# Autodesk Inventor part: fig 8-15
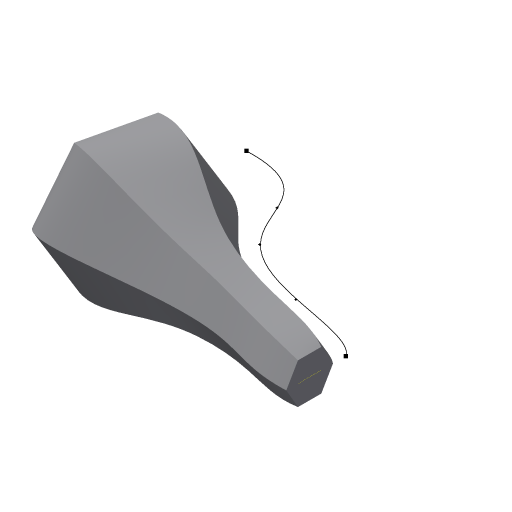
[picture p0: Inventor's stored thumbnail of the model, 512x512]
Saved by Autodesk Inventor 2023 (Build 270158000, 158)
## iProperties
Created: 2004-05
Part Number: fig 8-15
Document SubType Name: Modeling
Designer: CADCIM Technologies
Manufacturer: Standard
Standards Organization: Custom
Density: 1 g/cm^3
Material: Generic
Appearance: Default
Author: CADCIM Technologies
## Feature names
1. Sweep7
## Parameters: d6 = 0, d7 = 0
